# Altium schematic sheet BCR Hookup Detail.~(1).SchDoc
size B; Organization: Monterey Bay Aquarium Research Institute; Address1: 7700 Sandholdt Rd; Address2: Moss Landing, CA 95039-9644; CompanyName: MBARI
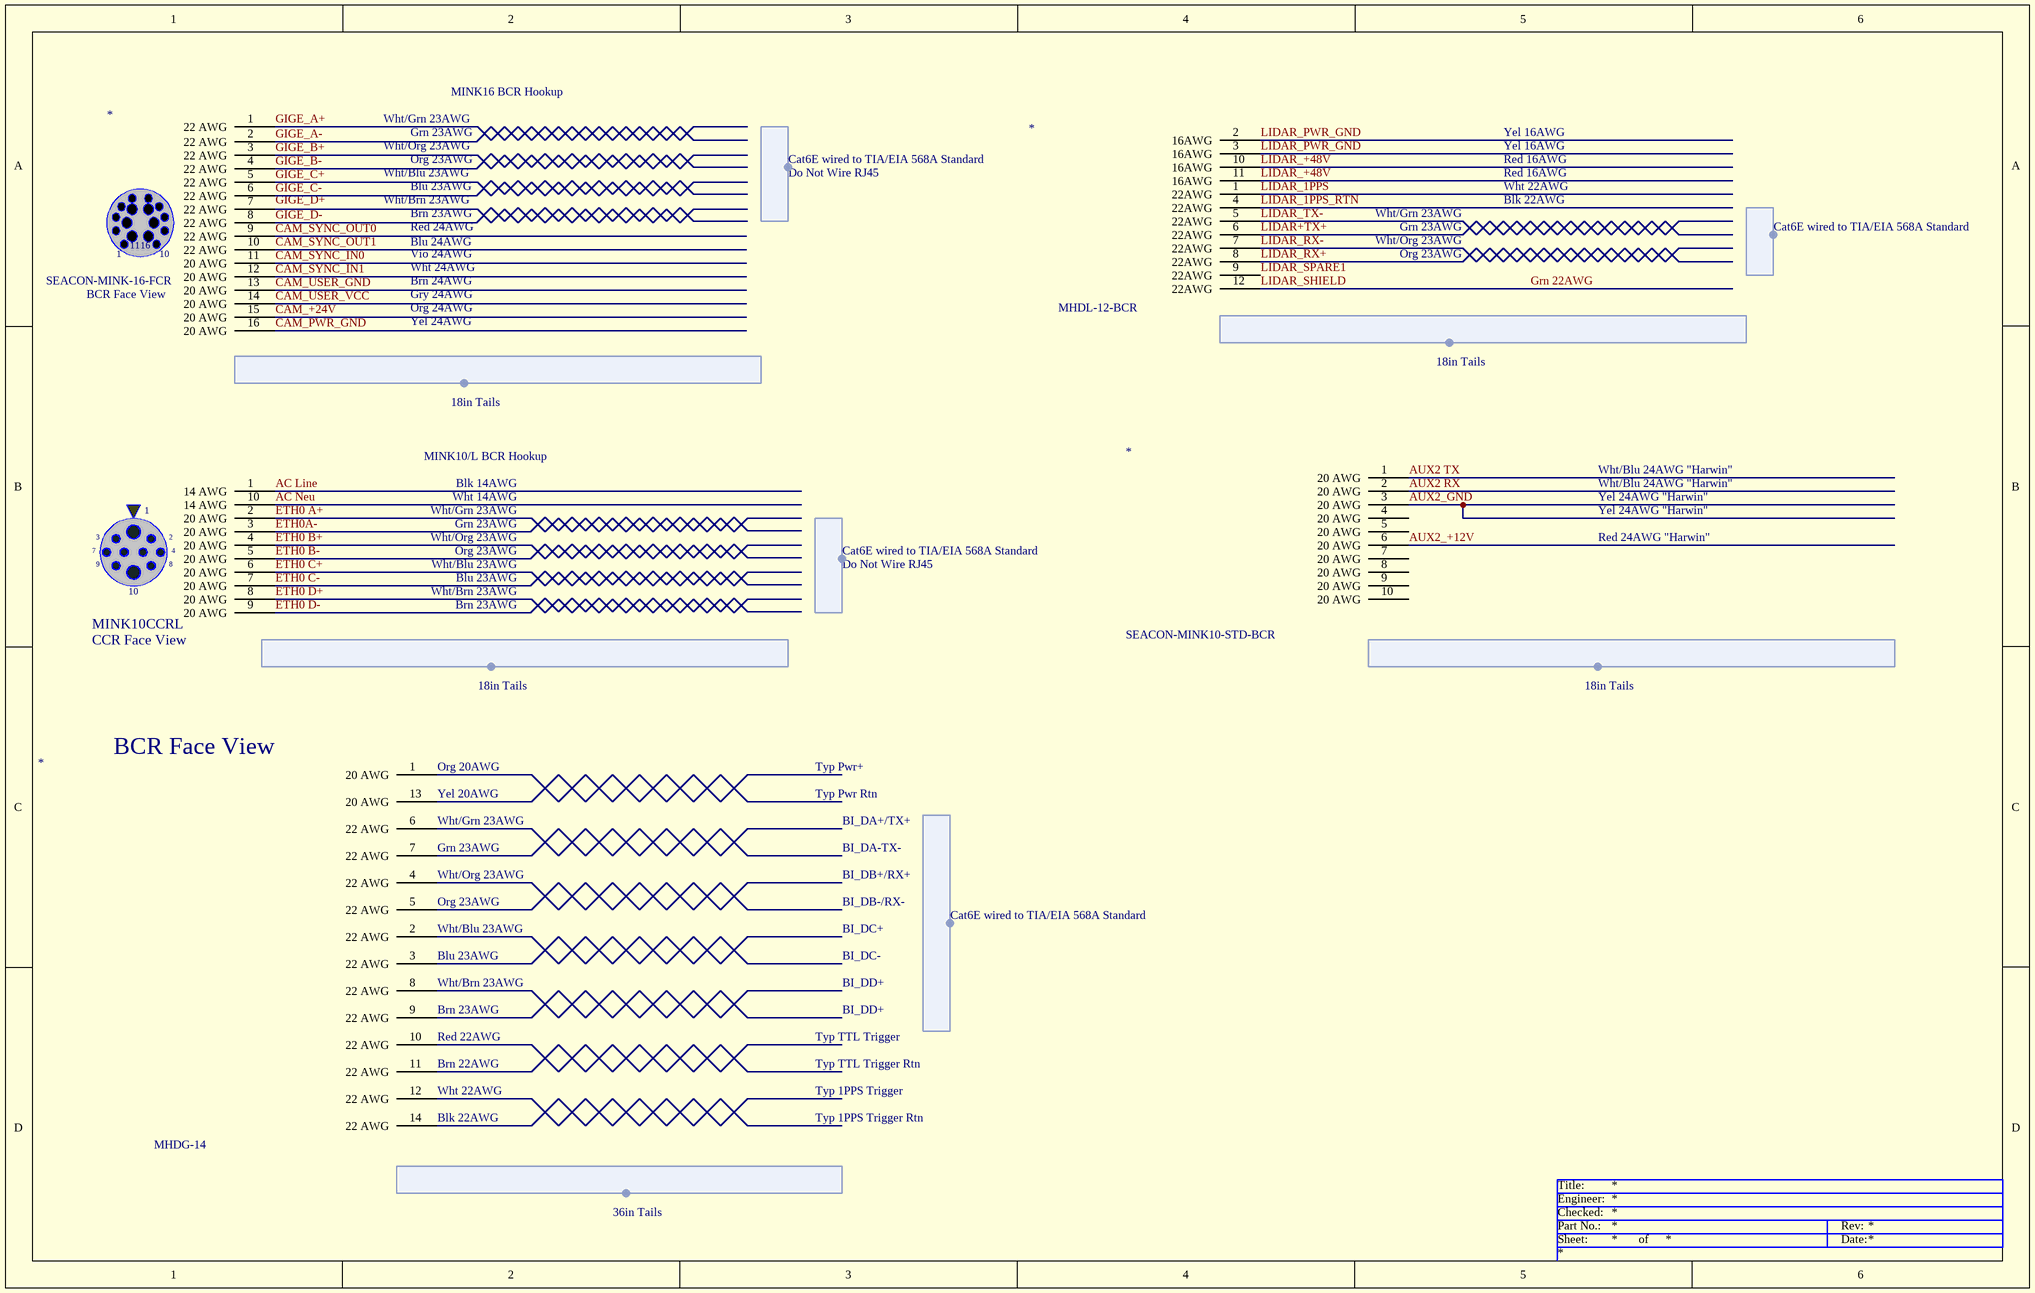
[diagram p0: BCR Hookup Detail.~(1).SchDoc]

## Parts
(Parts that share a designator on the sheet are numbered #1, #2 ... from top to bottom, then left to right.)
*#1  MHDL-12-BCR
*#2  SEACON-MINK-16-FCR
*#3  SEACON-MINK10-STD-BCR
*#4  MHDG-14
J?  MINK10CCRL  View: CCR Face View

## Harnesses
Cat6E wired to TIA/EIA 568A Standard: 
18in Tails: 
36in Tails: 

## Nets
AC Line: J?.1(14_AWG)
AC Neu: J?.10(14_AWG)
AUX2 RX: *#3.2(20_AWG)
AUX2 TX: *#3.1(20_AWG)
AUX2_+12V: *#3.6(20_AWG)
AUX2_GND: *#3.3(20_AWG)
CAM_+24V: *#2.15(20_AWG)
CAM_PWR_GND: *#2.16(20_AWG)
CAM_SYNC_IN0: *#2.11(20_AWG)
CAM_SYNC_IN1: *#2.12(20_AWG)
CAM_SYNC_OUT0: *#2.9(22_AWG)
CAM_SYNC_OUT1: *#2.10(22_AWG)
CAM_USER_GND: *#2.13(20_AWG)
CAM_USER_VCC: *#2.14(20_AWG)
ETH0 A+: J?.2(20_AWG)
ETH0 B+: J?.4(20_AWG)
ETH0 B-: J?.5(20_AWG)
ETH0 C+: J?.6(20_AWG)
ETH0 C-: J?.7(20_AWG)
ETH0 D+: J?.8(20_AWG)
ETH0 D-: J?.9(20_AWG)
ETH0A-: J?.3(20_AWG)
GIGE_A+: *#2.1(22_AWG)
GIGE_A-: *#2.2(22_AWG)
GIGE_B+: *#2.3(22_AWG)
GIGE_B-: *#2.4(22_AWG)
GIGE_C+: *#2.5(22_AWG)
GIGE_C-: *#2.6(22_AWG)
GIGE_D-: *#2.8(22_AWG)
Grn 22AWG: *#1.12(22AWG)  [also labelled LIDAR_SHIELD]
LIDAR+TX+: *#1.6(22AWG)
LIDAR_1PPS: *#1.1(22AWG)
LIDAR_1PPS_RTN: *#1.4(22AWG)
LIDAR_+48V: *#1.10(16AWG) *#1.11(16AWG)
LIDAR_PWR_GND: *#1.2(16AWG) *#1.3(16AWG)
LIDAR_RX+: *#1.8(22AWG)
LIDAR_RX-: *#1.7(22AWG)
LIDAR_SPARE1: *#1.9(22AWG)
LIDAR_TX-: *#1.5(22AWG)

Not connected (* = marked no-connect by the designer): *#2 7(22_AWG); *#3 4(20_AWG) 5(20_AWG) 7(20_AWG) 8(20_AWG) 9(20_AWG) 10(20_AWG); *#4 1(20_AWG) 2(22_AWG) 3(22_AWG) 4(22_AWG) 5(22_AWG) 6(22_AWG) 7(22_AWG) 8(22_AWG) 9(22_AWG) 10(22_AWG) 11(22_AWG) 12(22_AWG) 13(20_AWG) 14(22_AWG)

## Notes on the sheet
- MINK16 BCR Hookup
- Wht/Grn 23AWG
- Wht/Org 23AWG
- Grn 23AWG
- Org 23AWG
- Yel 16AWG
- Red 16AWG
- Wht/Blu 23AWG
- Wht/Brn 23AWG
- Blu 23AWG
- Brn 23AWG
- Red 24AWG
- Do Not Wire RJ45
- Wht 22AWG
- Blk 22AWG
- BCR Face View
- Wht 24AWG
- Brn 24AWG
- Gry 24AWG
- Blu 24AWG
- Vio 24AWG
- Yel 24AWG
- Org 24AWG
- MINK10/L BCR Hookup
- Blk 14AWG
- Wht 14AWG
- Wht/Blu 24AWG "Harwin"
- Yel 24AWG "Harwin"
- Red 24AWG "Harwin"
- (near *#4) Org 20AWG
- Typ Pwr+
- (near *#4) Yel 20AWG
- (near *#4) Wht/Grn 23AWG
- Typ Pwr Rtn
- BI_DA+/TX+
- (near *#4) Grn 23AWG
- (near *#4) Wht/Org 23AWG
- (near *#4) Org 23AWG
- BI_DA-TX-
- BI_DB+/RX+
- BI_DB-/RX-
- (near *#4) Wht/Blu 23AWG
- (near *#4) Blu 23AWG
- BI_DC+
- BI_DC-
- (near *#4) Wht/Brn 23AWG
- (near *#4) Brn 23AWG
- (near *#4) Red 22AWG
- Typ TTL Trigger
- BI_DD+
- (near *#4) Brn 22AWG
- (near *#4) Wht 22AWG
- Typ TTL Trigger Rtn
- Typ 1PPS Trigger
- (near *#4) Blk 22AWG
- Typ 1PPS Trigger Rtn
- Labels drawn without touching a wire or pin: GIGE_D+

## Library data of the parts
*#1 = MHDL-12-BCR: Impulse MHDL12 BCR
*#2 = SEACON-MINK-16-FCR: Seacon MINK-16 FCR
*#3 = SEACON-MINK10-STD-BCR: Seacon MINK10 BCR Standard Length
J? = SEACON-MINK-10/L CCR (SMALL): Seacon MINK-10/L-CCR Molded to C/F Falmat Cable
